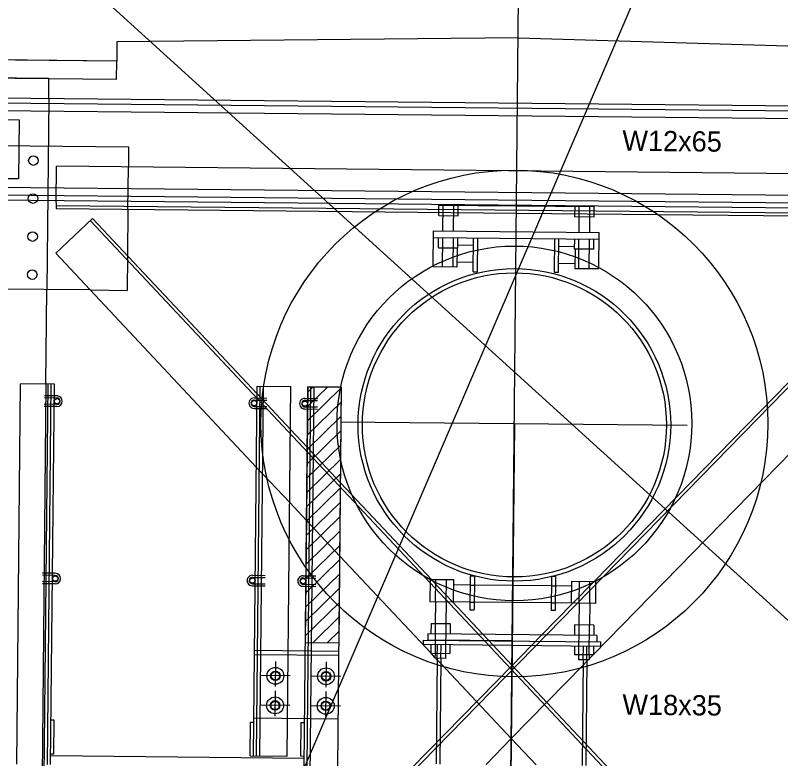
# Model space of a CAD drawing. Extents: x 632312 to 632885, y 378199 to 378534.
# Drawn here: x 632723.43 to 632730.99, y 378453.59 to 378460.93 of the extents above; entities that cross this region are included whole.
import ezdxf

# ---------------------------------------------------------------- set-up
doc = ezdxf.new("R2010")
doc.units = 0
for name, color, linetype in [('B_Boring', 7, 'Continuous'), ('B_Boring Annot', 7, 'Continuous'), ('BDR-SHEET_TITLE', 7, 'Continuous'), ('R_Border', 7, 'Continuous'), ('R_Proposed Const Limits Cut', 7, 'Continuous'), ('R_Road Edge of Shoulder', 7, 'Continuous'), ('SHT_Dimensions', 7, 'Continuous'), ('USACE_Easement', 7, 'Continuous')]:
    doc.layers.add(name, color=color, linetype=linetype)

msp = doc.modelspace()

# ---------------------------------------------------------------- linework, layer by layer
at = {"layer": 'B_Boring'}
for p, q in [((632733.8893, 378459.9542), (632722.8899, 378460.0636)), ((632733.8898, 378460.0046), (632722.8904, 378460.114)), ((632722.8049, 378459.9023), (632723.4716, 378459.8957)), ((632723.4716, 378459.8957), (632723.4658, 378459.3124)), ((632724.5523, 378459.6297), (632724.5523, 378459.6297)), ((632723.4658, 378459.3124), (632722.7991, 378459.319)), ((632733.8803, 378459.0467), (632722.8808, 378459.1561)), ((632733.8798, 378458.9963), (632722.8803, 378459.1057)), ((632723.8385, 378459.0805), (632723.8379, 378459.0201)), ((632723.8379, 378459.0201), (632728.3793, 378458.975)), ((632727.6131, 378458.9513), (632727.6142, 378459.0586)), ((632729.1459, 378459.0362), (632727.6141, 378459.0514)), ((632727.6538, 378458.7982), (632727.6564, 378459.0582)), ((632727.7586, 378458.7972), (632727.7612, 378459.0572)), ((632727.8023, 378458.9494), (632727.8034, 378459.0567)), ((632728.9557, 378458.9379), (632728.9568, 378459.0453)), ((632728.9964, 378458.7849), (632728.999, 378459.0449)), ((632729.1012, 378458.7838), (632729.1038, 378459.0438)), ((632729.1449, 378458.9361), (632729.146, 378459.0434)), ((632727.6131, 378458.9513), (632727.8023, 378458.9494)), ((632728.3793, 378458.975), (632732.9208, 378458.9298)), ((632729.1449, 378458.9361), (632728.9557, 378458.9379)), ((632727.5577, 378458.4442), (632727.5613, 378458.7991)), ((632727.5613, 378458.7991), (632729.1937, 378458.7829)), ((632729.1902, 378458.428), (632729.1937, 378458.7829)), ((632727.5606, 378458.7359), (632729.1931, 378458.7197)), ((632727.61, 378458.6333), (632727.611, 378458.7354)), ((632727.6503, 378458.4433), (632727.6532, 378458.735)), ((632727.7551, 378458.4423), (632727.758, 378458.734)), ((632727.7991, 378458.6314), (632727.8001, 378458.7336)), ((632727.9522, 378458.3962), (632727.9555, 378458.732)), ((632727.9933, 378458.3958), (632727.9966, 378458.7316)), ((632728.7538, 378458.3882), (632728.7571, 378458.724)), ((632728.7948, 378458.3878), (632728.7982, 378458.7236)), ((632728.9526, 378458.62), (632728.9536, 378458.7221)), ((632728.9929, 378458.43), (632728.9958, 378458.7217)), ((632729.0977, 378458.4289), (632729.1006, 378458.7206)), ((632729.1417, 378458.6181), (632729.1427, 378458.7202)), ((632727.61, 378458.6333), (632727.7991, 378458.6314)), ((632727.7937, 378458.6315), (632727.7919, 378458.4419)), ((632727.9548, 378458.6571), (632727.7994, 378458.6586)), ((632728.7974, 378458.6487), (632728.9528, 378458.6472)), ((632729.1417, 378458.6181), (632728.9526, 378458.62)), ((632728.958, 378458.6199), (632728.9561, 378458.4303)), ((632727.9531, 378458.4891), (632727.7923, 378458.4907)), ((632728.7958, 378458.4807), (632728.9566, 378458.4791)), ((632727.7919, 378458.4419), (632727.5577, 378458.4442)), ((632727.9522, 378458.3962), (632727.9933, 378458.3958)), ((632728.7948, 378458.3878), (632728.7538, 378458.3882)), ((632728.9561, 378458.4303), (632729.1902, 378458.428)), ((632724.1734, 378458.2168), (632723.1633, 378458.2268)), ((632723.45, 378453.5399), (632723.4873, 378457.2897)), ((632723.8206, 378457.2864), (632723.4873, 378457.2897)), ((632723.7521, 378453.5369), (632723.7894, 378457.2867)), ((632723.7834, 378453.5366), (632723.8206, 378457.2864)), ((632725.7843, 378453.6209), (632725.8205, 378457.2665)), ((632725.8155, 378453.6206), (632725.8518, 378457.2662)), ((632725.8205, 378457.2665), (632726.1539, 378457.2632)), ((632726.1176, 378453.6176), (632726.1539, 378457.2632)), ((632726.2832, 378453.5118), (632726.3205, 378457.2616)), ((632726.3145, 378453.5115), (632726.3518, 378457.2613)), ((632726.3172, 378456.9252), (632726.6538, 378457.2552)), ((632726.3186, 378457.0666), (632726.5155, 378457.2596)), ((632726.32, 378457.208), (632726.3741, 378457.261)), ((632726.3205, 378457.2616), (632726.6538, 378457.2583)), ((632726.6166, 378453.5084), (632726.6538, 378457.2583)), ((632723.8469, 378457.1507), (632723.7219, 378457.152)), ((632723.8471, 378457.1716), (632723.7221, 378457.1728)), ((632725.7916, 378457.1314), (632725.9165, 378457.1302)), ((632725.7918, 378457.1522), (632725.9168, 378457.151)), ((632726.2915, 378457.1264), (632726.4165, 378457.1252)), ((632726.2917, 378457.1473), (632726.4167, 378457.146)), ((632726.3158, 378456.7838), (632726.6524, 378457.1138)), ((632723.8461, 378457.0674), (632723.7211, 378457.0687)), ((632723.8463, 378457.0883), (632723.7213, 378457.0895)), ((632725.7907, 378457.0481), (632725.9157, 378457.0468)), ((632725.7909, 378457.0689), (632725.9159, 378457.0677)), ((632726.2907, 378457.0431), (632726.4157, 378457.0419)), ((632726.2909, 378457.0639), (632726.4159, 378457.0627)), ((632726.3144, 378456.6424), (632726.651, 378456.9724)), ((632726.313, 378456.5009), (632726.6496, 378456.8309)), ((632726.3115, 378456.3595), (632726.6482, 378456.6895)), ((632726.3101, 378456.2181), (632726.6468, 378456.5481)), ((632726.3087, 378456.0767), (632726.6454, 378456.4067)), ((632726.3073, 378455.9353), (632726.644, 378456.2653)), ((632726.3059, 378455.7939), (632726.6426, 378456.1239)), ((632726.3045, 378455.6525), (632726.6411, 378455.9825)), ((632726.3031, 378455.511), (632726.6397, 378455.841)), ((632726.3017, 378455.3696), (632726.6383, 378455.6996)), ((632726.3003, 378455.2282), (632726.6369, 378455.5582)), ((632725.7742, 378455.3815), (632725.8992, 378455.3803)), ((632725.7744, 378455.4023), (632725.8994, 378455.4011)), ((632726.2989, 378455.0868), (632726.6355, 378455.4168)), ((632727.9224, 378455.3983), (632727.9191, 378455.0624)), ((632727.9224, 378455.3983), (632727.9635, 378455.3978)), ((632727.9635, 378455.3978), (632727.9601, 378455.062)), ((632728.724, 378455.3903), (632728.7206, 378455.0545)), ((632728.765, 378455.3899), (632728.724, 378455.3903)), ((632728.765, 378455.3899), (632728.7617, 378455.0541)), ((632725.7733, 378455.2982), (632725.8983, 378455.2969)), ((632725.7735, 378455.319), (632725.8985, 378455.3178)), ((632727.5271, 378455.3581), (632727.5249, 378455.1413)), ((632727.7612, 378455.3558), (632727.5271, 378455.3581)), ((632727.759, 378455.139), (632727.7612, 378455.3558)), ((632727.9215, 378455.3054), (632727.7607, 378455.307)), ((632728.723, 378455.2974), (632727.9625, 378455.3049)), ((632728.9249, 378455.2954), (632728.7641, 378455.297)), ((632728.9232, 378455.1274), (632728.9254, 378455.3442)), ((632728.9254, 378455.3442), (632729.1595, 378455.3418)), ((632729.1595, 378455.3418), (632729.1573, 378455.1251)), ((632726.2975, 378454.9454), (632726.6341, 378455.2754)), ((632727.9198, 378455.1374), (632727.5249, 378455.1413)), ((632727.5804, 378455.1407), (632727.5783, 378454.9272)), ((632727.6852, 378455.1397), (632727.6831, 378454.9262)), ((632726.2961, 378454.804), (632726.6327, 378455.134)), ((632727.9191, 378455.0624), (632727.9601, 378455.062)), ((632728.7214, 378455.1294), (632727.9609, 378455.137)), ((632729.1573, 378455.1251), (632728.7624, 378455.129)), ((632728.997, 378455.1267), (632728.9949, 378454.9132)), ((632729.1018, 378455.1256), (632729.0997, 378454.9121)), ((632726.3726, 378454.739), (632726.6313, 378454.9926)), ((632728.7617, 378455.0541), (632728.7206, 378455.0545)), ((632727.5361, 378454.9277), (632727.5351, 378454.8255)), ((632727.5361, 378454.9277), (632727.7253, 378454.9258)), ((632727.7253, 378454.9258), (632727.7243, 378454.8237)), ((632728.9527, 378454.9136), (632728.9517, 378454.8114)), ((632729.1419, 378454.9117), (632728.9527, 378454.9136)), ((632729.1419, 378454.9117), (632729.1409, 378454.8096)), ((632726.5141, 378454.7376), (632726.6299, 378454.8511)), ((632727.462, 378454.7214), (632727.4624, 378454.7631)), ((632727.4624, 378454.7631), (632729.2123, 378454.7457)), ((632727.5047, 378454.8258), (632727.5041, 378454.7626)), ((632729.1713, 378454.8093), (632727.5047, 378454.8258)), ((632729.1713, 378454.8093), (632729.1706, 378454.7461)), ((632727.462, 378454.7214), (632729.2119, 378454.704)), ((632727.5341, 378454.7207), (632727.5332, 378454.6326)), ((632727.7232, 378454.7188), (632727.7224, 378454.6308)), ((632728.9507, 378454.7066), (632728.9498, 378454.6186)), ((632729.1398, 378454.7047), (632729.139, 378454.6167)), ((632729.2119, 378454.704), (632729.2123, 378454.7457)), ((632725.7942, 378454.6208), (632726.6275, 378454.6126)), ((632725.7946, 378454.6625), (632726.6279, 378454.6542)), ((632727.5332, 378454.6326), (632727.7224, 378454.6308)), ((632727.5754, 378454.6322), (632727.5749, 378454.5832)), ((632727.6802, 378454.6312), (632727.6797, 378454.5822)), ((632729.139, 378454.6167), (632728.9498, 378454.6186)), ((632728.992, 378454.6181), (632728.9915, 378454.5691)), ((632729.0968, 378454.6171), (632729.0963, 378454.5681)), ((632727.6797, 378454.5822), (632727.5749, 378454.5832)), ((632727.5981, 378454.583), (632727.5877, 378453.5405)), ((632727.6335, 378454.5826), (632727.6232, 378453.5401)), ((632729.0963, 378454.5681), (632728.9915, 378454.5691)), ((632729.0376, 378454.5687), (632729.0273, 378453.5261)), ((632729.073, 378454.5683), (632729.0627, 378453.5258)), ((632723.819, 378453.9738), (632723.7877, 378453.9741)), ((632723.8156, 378453.6405), (632723.819, 378453.9738)), ((632725.753, 378453.6212), (632725.7564, 378453.9545)), ((632725.7564, 378453.9545), (632725.7876, 378453.9542)), ((632725.788, 378453.9959), (632726.6213, 378453.9876)), ((632726.253, 378453.6162), (632726.2563, 378453.9496)), ((632726.2563, 378453.9496), (632726.2876, 378453.9492)), ((632723.7844, 378453.6408), (632723.8156, 378453.6405)), ((632726.2841, 378453.5951), (632723.7842, 378453.6199)), ((632725.753, 378453.6212), (632726.1176, 378453.6176)), ((632726.2843, 378453.6159), (632726.253, 378453.6162))]:
    msp.add_line(p, q, dxfattribs=at)
for points in [[(632724.4339, 378460.2976), (632724.4357, 378460.4747), (632721.1025, 378460.5078), (632721.1008, 378460.3308)], [(632726.6538, 378457.2583), (632726.3205, 378457.2616), (632726.2954, 378454.7398), (632726.6288, 378454.7364)]]:
    msp.add_lwpolyline(points, close=True, dxfattribs=at)
for points in [[(632723.7653, 378460.1053), (632723.7673, 378460.3042), (632722.809, 378460.3138), (632722.6897, 378448.3144), (632723.648, 378448.3048), (632723.6492, 378448.4298)], [(632724.5462, 378459.0131), (632724.5416, 378458.5551)], [(632725.8126, 378456.4703), (632723.8335, 378458.579), (632724.1981, 378458.9212), (632725.8198, 378457.1933)], [(632729.139, 378454.6211), (632732.9164, 378458.4887), (632732.5587, 378458.838), (632729.1441, 378455.342)], [(632723.7373, 378457.2873), (632723.7466, 378458.221)], [(632726.1497, 378456.8418), (632726.3146, 378456.6661)], [(632726.6445, 378456.3147), (632727.5424, 378455.3579)], [(632726.3074, 378455.9431), (632726.1425, 378456.1189)], [(632727.5332, 378454.6371), (632726.6373, 378455.5917)], [(632727.7478, 378455.1391), (632728.0469, 378454.8204)], [(632728.9344, 378455.1273), (632728.619, 378454.8043)], [(632728.5277, 378454.7108), (632728.335, 378454.5135), (632727.3463, 378453.5012)], [(632728.1462, 378454.7146), (632728.335, 378454.5135)], [(632727.575, 378454.5926), (632727.5375, 378454.6326)], [(632729.0964, 378454.5775), (632729.1347, 378454.6167)], [(632727.598, 378454.5681), (632727.5839, 378454.5831)], [(632729.0729, 378454.5535), (632729.0873, 378454.5682)], [(632727.9853, 378454.1555), (632727.633, 378454.5308)], [(632728.0788, 378453.5356), (632728.3278, 378453.7905), (632729.0371, 378454.5168)], [(632728.6775, 378454.1486), (632729.3033, 378453.4817)], [(632728.5717, 378453.5307), (632728.3278, 378453.7905)]]:
    msp.add_lwpolyline(points, dxfattribs=at)
for centre, radius in [((632723.6134, 378459.4932), 0.0469), ((632723.6097, 378459.1183), 0.0469), ((632723.6059, 378458.7433), 0.0469), ((632723.6022, 378458.3683), 0.0469), ((632728.3585, 378456.886), 1.5417), ((632728.3585, 378456.886), 1.5), ((632723.8466, 378457.1195), 0.026), ((632725.7912, 378457.1002), 0.0261), ((632725.7738, 378455.3503), 0.0261), ((632726.0005, 378454.4105), 0.0469), ((632726.5005, 378454.4055), 0.0469), ((632725.9976, 378454.1188), 0.0469), ((632726.4976, 378454.1138), 0.0469)]:
    msp.add_circle(centre, radius, dxfattribs=at)
for centre, radius, start, end in [((632723.8466, 378457.1195), 0.0521, 269.43036, 89.43036), ((632723.8466, 378457.1195), 0.0312, 269.43036, 89.43036), ((632725.7912, 378457.1002), 0.0521, 89.43036, 269.43036), ((632725.7912, 378457.1002), 0.0312, 89.43036, 269.43036), ((632726.2912, 378457.0952), 0.0521, 89.43036, 269.43036), ((632726.2912, 378457.0952), 0.0312, 89.43036, 269.43036), ((632725.7738, 378455.3503), 0.0521, 89.43036, 269.43036), ((632725.7738, 378455.3503), 0.0312, 89.43036, 269.43036)]:
    msp.add_arc(centre, radius, start, end, dxfattribs=at)
at = {"layer": 'B_Boring Annot'}
for p, q in [((632724.4376, 378460.6643), (632724.4357, 378460.4747)), ((632728.3965, 378460.7041), (632724.4376, 378460.6643)), ((632728.3965, 378460.7041), (632732.3539, 378460.5856)), ((632724.4357, 378460.4747), (632721.1025, 378460.5078))]:
    msp.add_line(p, q, dxfattribs=at)
at = {"layer": 'BDR-SHEET_TITLE'}
for p, q in [((632726.0019, 378454.5529), (632725.9994, 378454.3048)), ((632726.5019, 378454.5479), (632726.4994, 378454.2998)), ((632726.1472, 378454.409), (632725.8495, 378454.412)), ((632726.6471, 378454.404), (632726.3495, 378454.407)), ((632725.999, 378454.2613), (632725.9965, 378454.0131)), ((632726.499, 378454.2563), (632726.4965, 378454.0082)), ((632726.1443, 378454.1173), (632725.8466, 378454.1203)), ((632726.6442, 378454.1124), (632726.3466, 378454.1153))]:
    msp.add_line(p, q, dxfattribs=at)
at = {"layer": 'R_Border'}
for radius in [2.5, 1.75]:
    msp.add_circle((632728.3587, 378456.9001), radius, dxfattribs=at)
at = {"layer": 'R_Proposed Const Limits Cut'}
for p, q in [((632723.7653, 378460.1053), (632723.7466, 378458.221)), ((632733.8886, 378459.8796), (632722.8891, 378459.989)), ((632723.1774, 378459.6434), (632724.5523, 378459.6297)), ((632724.5523, 378459.6297), (632724.5503, 378459.4298)), ((632723.8385, 378459.0805), (632723.842, 378459.4368)), ((632732.9249, 378459.3465), (632723.842, 378459.4368)), ((632724.5462, 378459.0131), (632724.5503, 378459.4298)), ((632733.881, 378459.1213), (632722.8816, 378459.2307)), ((632732.921, 378458.9559), (632723.8381, 378459.0462)), ((632724.1753, 378458.8998), (632732.8065, 378449.7037)), ((632732.581, 378458.8162), (632723.7687, 378449.7935)), ((632724.5416, 378458.5551), (632724.5382, 378458.2131)), ((632724.1734, 378458.2168), (632724.5382, 378458.2131)), ((632723.7373, 378457.2873), (632723.6846, 378451.9875)), ((632723.7124, 378452.6831), (632723.7581, 378457.2871)), ((632725.8468, 378453.6203), (632725.883, 378457.2659)), ((632726.3372, 378452.657), (632726.383, 378457.261)), ((632726.1497, 378456.8418), (632725.8198, 378457.1933)), ((632726.3146, 378456.6661), (632726.6445, 378456.3147)), ((632726.1425, 378456.1189), (632725.8126, 378456.4703)), ((632726.3074, 378455.9431), (632726.6373, 378455.5917)), ((632727.749, 378455.1391), (632727.5423, 378455.3579)), ((632727.5804, 378455.1407), (632727.5826, 378455.3575)), ((632727.6852, 378455.1397), (632727.6874, 378455.3565)), ((632727.9215, 378455.3054), (632727.9625, 378455.3049)), ((632728.723, 378455.2974), (632728.7641, 378455.297)), ((632728.9344, 378455.1273), (632729.1441, 378455.342)), ((632728.997, 378455.1267), (632728.9992, 378455.3434)), ((632729.1018, 378455.1256), (632729.104, 378455.3424)), ((632727.9198, 378455.1374), (632727.9609, 378455.137)), ((632728.7214, 378455.1294), (632728.7624, 378455.129)), ((632727.5783, 378454.9272), (632727.5754, 378454.6322)), ((632727.6831, 378454.9262), (632727.6802, 378454.6312)), ((632728.9949, 378454.9132), (632728.992, 378454.6181)), ((632729.0968, 378454.6171), (632729.0997, 378454.9121)), ((632728.1462, 378454.7146), (632728.0469, 378454.8204)), ((632728.5277, 378454.7108), (632728.619, 378454.8043)), ((632727.5981, 378454.583), (632727.5995, 378454.72)), ((632727.6335, 378454.5826), (632727.6349, 378454.7197)), ((632729.0376, 378454.5687), (632729.039, 378454.7057)), ((632729.073, 378454.5683), (632729.0744, 378454.7054)), ((632727.5332, 378454.6371), (632727.5375, 378454.6326)), ((632729.1347, 378454.6167), (632729.139, 378454.6211)), ((632727.575, 378454.5926), (632727.5839, 378454.5831)), ((632727.598, 378454.5681), (632727.633, 378454.5308)), ((632729.0371, 378454.5168), (632729.0729, 378454.5535)), ((632729.0873, 378454.5682), (632729.0964, 378454.5775)), ((632728.6775, 378454.1486), (632728.335, 378454.5135)), ((632727.9853, 378454.1555), (632728.3278, 378453.7905))]:
    msp.add_line(p, q, dxfattribs=at)
for centre, radius in [((632726.0005, 378454.4105), 0.0833), ((632726.5005, 378454.4055), 0.0833), ((632726.0005, 378454.4105), 0.0417), ((632726.5005, 378454.4055), 0.0417), ((632725.9976, 378454.1188), 0.0833), ((632725.9976, 378454.1188), 0.0417), ((632726.4976, 378454.1138), 0.0833), ((632726.4976, 378454.1138), 0.0417)]:
    msp.add_circle(centre, radius, dxfattribs=at)
at = {"layer": 'R_Road Edge of Shoulder'}
msp.add_line((632728.2284, 378443.7915), (632728.5589, 378477.0332), dxfattribs=at)
at = {"layer": 'SHT_Dimensions'}
for p, q in [((632726.643, 378456.9171), (632730.0635, 378456.8831)), ((632728.3586, 378456.8897), (632728.3207, 378453.0781)), ((632723.8295, 378455.4008), (632723.7045, 378455.4021)), ((632723.8297, 378455.4217), (632723.7047, 378455.4229)), ((632726.2741, 378455.3765), (632726.3991, 378455.3753)), ((632726.2743, 378455.3974), (632726.3993, 378455.3961)), ((632723.8287, 378455.3175), (632723.7037, 378455.3187)), ((632723.8289, 378455.3383), (632723.7039, 378455.3396)), ((632726.2733, 378455.2932), (632726.3983, 378455.292)), ((632726.2735, 378455.314), (632726.3985, 378455.3128)), ((632728.3374, 378454.7544), (632727.5041, 378454.7626))]:
    msp.add_line(p, q, dxfattribs=at)
for centre, radius in [((632726.2912, 378457.0952), 0.0261), ((632723.8292, 378455.3696), 0.026), ((632726.2738, 378455.3453), 0.0261)]:
    msp.add_circle(centre, radius, dxfattribs=at)
for centre, radius, start, end in [((632723.8292, 378455.3696), 0.0521, 269.43036, 89.43036), ((632723.8292, 378455.3696), 0.0312, 269.43036, 89.43036), ((632726.2738, 378455.3453), 0.0521, 89.43036, 269.43036), ((632726.2738, 378455.3453), 0.0312, 89.43036, 269.43036)]:
    msp.add_arc(centre, radius, start, end, dxfattribs=at)
at = {"layer": 'USACE_Easement'}
for p, q in [((632721.1425, 378441.516), (632733.2478, 378469.724)), ((632719.1834, 378465.7384), (632748.8898, 378438.7648))]:
    msp.add_line(p, q, dxfattribs=at)

# ---------------------------------------------------------------- texts
at = {"layer": 'SHT_Dimensions'}
for s, p in [('W12x65', (632729.4229, 378459.5905)), ('W18x35', (632729.4233, 378454.0274))]:
    msp.add_text(s, height=0.2, rotation=359.43036, dxfattribs=at).set_placement(p)

doc.saveas('drawing.dxf')
